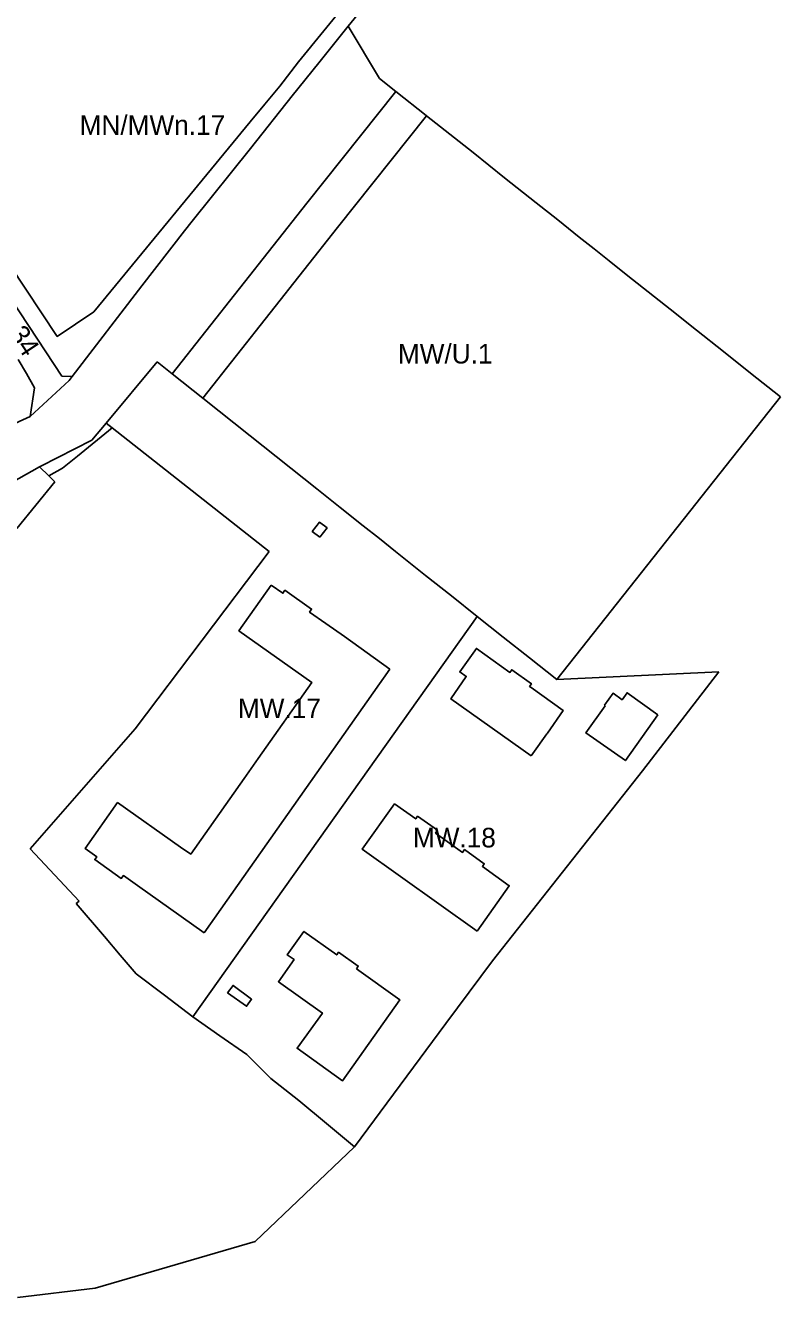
# Model space of a CAD drawing. Extents: x 7425067 to 7426806, y 5549054 to 5550619.
# Drawn here: x 7426541.6 to 7426734.3, y 5549087.4 to 5549411.9 of the extents above; entities that cross this region are included whole.
import ezdxf

# ---------------------------------------------------------------- set-up
doc = ezdxf.new("R2010")
doc.units = 0
for name, color, linetype in [('LIN_Linia Zabudowy Nieprzekraczalna', 7, 'Continuous'), ('LIN_linia zabudowy obowiązująca', 7, 'Continuous'), ('LIN_linie_rozgraniczajace', 7, 'Continuous'), ('TXT_Oznaczenia_przeznaczen', 7, 'Continuous')]:
    doc.layers.add(name, color=color, linetype=linetype)

msp = doc.modelspace()

# ---------------------------------------------------------------- linework, layer by layer
at = {"layer": 'LIN_Linia Zabudowy Nieprzekraczalna'}
for points in [[(7426559.05, 5549338.85), (7426598.94, 5549387.25), (7426602.65, 5549391.8), (7426606.54, 5549396.35), (7426611.3, 5549402.56), (7426623.41, 5549417.42)], [(7426509.4701, 5549393.1024), (7426549.7, 5549332.54), (7426559.05, 5549338.85)], [(7426643.961, 5549388.8438), (7426621.2029, 5549360.3434), (7426586.8566, 5549316.8017)], [(7426563.6817, 5549309.2654), (7426554.9095, 5549301.9812), (7426551.0535, 5549298.9547), (7426547.549, 5549296.9622)]]:
    msp.add_lwpolyline(points, dxfattribs=at)
at = {"layer": 'LIN_linia zabudowy obowiązująca'}
for points in [[(7426616.69, 5549281.34), (7426618.56, 5549283.7), (7426616.65, 5549285.2), (7426614.79, 5549282.84), (7426616.69, 5549281.34)], [(7426604.32, 5549269.15), (7426596.08, 5549257.47), (7426614.72, 5549244.29), (7426601.03, 5549224.89), (7426597.41, 5549219.8), (7426583.77, 5549200.51), (7426581.19, 5549202.33), (7426565.1, 5549213.65), (7426556.83, 5549201.99), (7426559.79, 5549199.83), (7426559.27, 5549199.13), (7426566.03, 5549194.32), (7426566.59, 5549195.06), (7426570.77, 5549192.09), (7426575.49, 5549188.76), (7426587.21, 5549180.44)], [(7426634.62, 5549247.73), (7426622.99, 5549256), (7426618.29, 5549259.3), (7426614.11, 5549262.27), (7426614.61, 5549263.01), (7426607.82, 5549267.8), (7426607.29, 5549267.07), (7426604.32, 5549269.15)], [(7426670.64, 5549225.56), (7426671.06, 5549226.15), (7426674.69, 5549231.23), (7426674.8, 5549231.41), (7426678.85, 5549237.13), (7426670.6318, 5549243.0425), (7426670.26, 5549243.31), (7426670.74, 5549243.98), (7426665.73, 5549247.54), (7426665.25, 5549246.87), (7426656.68, 5549252.97), (7426652.45, 5549247.01), (7426654.12, 5549245.83), (7426650.2, 5549240.12), (7426670.64, 5549225.56)], [(7426587.21, 5549180.44), (7426634.62, 5549247.73)], [(7426703.04, 5549236.06), (7426695.15, 5549241.68), (7426693.89, 5549239.91), (7426691.58, 5549241.54), (7426689.41, 5549238.49), (7426689.59, 5549238.37)], [(7426689.59, 5549238.37), (7426684.66, 5549231.42), (7426694.74, 5549224.37), (7426703.04, 5549236.06)], [(7426656.9, 5549180.9), (7426665.09, 5549192.46), (7426658.22, 5549197.38), (7426658.69, 5549198.05), (7426653.67, 5549201.68), (7426653.17, 5549200.97), (7426646.27, 5549205.88), (7426646.75, 5549206.59), (7426641.68, 5549210.18), (7426641.2, 5549209.5), (7426635.8, 5549213.33), (7426627.57, 5549201.75), (7426656.9, 5549180.9)], [(7426626.06, 5549171.24), (7426626.55, 5549171.97), (7426621.52, 5549175.5), (7426621.04, 5549174.83), (7426612.66, 5549180.79), (7426608.43, 5549174.83), (7426610.14, 5549173.62), (7426606.15, 5549167.99), (7426617.39, 5549160), (7426610.92, 5549151), (7426622.53, 5549142.72), (7426637.17, 5549163.35), (7426626.06, 5549171.24)], [(7426593.17, 5549165.17), (7426598.02, 5549161.74), (7426599.29, 5549163.49), (7426594.57, 5549167.02), (7426593.17, 5549165.17)]]:
    msp.add_lwpolyline(points, dxfattribs=at)
at = {"layer": 'LIN_linie_rozgraniczajace'}
for points in [[(7426626.2246, 5549414.4685), (7426623.958, 5549411.6537)], [(7426616.49, 5549402.36), (7426623.958, 5549411.6537)], [(7426623.958, 5549411.6537), (7426631.93, 5549398.36)], [(7426609.7, 5549393.89), (7426616.49, 5549402.36)], [(7426631.93, 5549398.36), (7426636.1178, 5549395.0476), (7426643.89, 5549388.9)], [(7426599.01, 5549380.5), (7426609.7, 5549393.89)], [(7426613.37, 5549366.56), (7426636.1178, 5549395.0476)], [(7426643.89, 5549388.9), (7426643.961, 5549388.8438), (7426655.85, 5549379.44)], [(7426584.13, 5549361.94), (7426599.01, 5549380.5)], [(7426655.85, 5549379.44), (7426663.89, 5549373.03)], [(7426663.89, 5549373.03), (7426671.93, 5549366.62)], [(7426579.0286, 5549323.0245), (7426613.37, 5549366.56)], [(7426671.93, 5549366.62), (7426677.44, 5549362.26)], [(7426582.16, 5549359.48), (7426584.13, 5549361.94)], [(7426677.44, 5549362.26), (7426682.94, 5549357.89)], [(7426571.27, 5549345.42), (7426582.16, 5549359.48)], [(7426682.94, 5549357.89), (7426686.75, 5549354.86)], [(7426686.75, 5549354.86), (7426690.57, 5549351.84)], [(7426690.57, 5549351.84), (7426694.95, 5549348.36)], [(7426552.72, 5549321.35), (7426553.4812, 5549322.3377), (7426571.27, 5549345.42)], [(7426694.95, 5549348.36), (7426699.34, 5549344.89)], [(7426537.79, 5549342.29), (7426544.645, 5549331.83)], [(7426699.34, 5549344.89), (7426706.11, 5549339.51)], [(7426706.11, 5549339.51), (7426712.88, 5549334.14)], [(7426712.88, 5549334.14), (7426719.76, 5549328.68)], [(7426544.645, 5549331.83), (7426550.8374, 5549322.381)], [(7426539.73, 5549326.66), (7426541.835, 5549323.065)], [(7426562.19, 5549310.44), (7426575.21, 5549326.06)], [(7426575.21, 5549326.06), (7426579.0286, 5549323.0245)], [(7426719.76, 5549328.68), (7426726.64, 5549323.22)], [(7426541.835, 5549323.065), (7426543.94, 5549319.47)], [(7426598.91, 5549307.22), (7426586.8566, 5549316.8017), (7426579.0286, 5549323.0245)], [(7426726.64, 5549323.22), (7426734.33, 5549317.11)], [(7426542.78, 5549312.14), (7426552.72, 5549321.35)], [(7426543.94, 5549319.47), (7426542.78, 5549312.14)], [(7426550.8374, 5549322.381), (7426553.4812, 5549322.3377)], [(7426734.33, 5549317.11), (7426677.18, 5549245.04)], [(7426542.78, 5549312.14), (7426532.06, 5549307.31)], [(7426558.54, 5549306.06), (7426562.19, 5549310.44)], [(7426562.19, 5549310.44), (7426563.6817, 5549309.2654), (7426582.98, 5549294.07)], [(7426598.91, 5549307.22), (7426615.95, 5549293.67)], [(7426545.49, 5549299.47), (7426558.54, 5549306.06)], [(7426536.6, 5549294.43), (7426545.2146, 5549299.3138), (7426545.49, 5549299.47)], [(7426545.2146, 5549299.3138), (7426547.549, 5549296.9622), (7426549.07, 5549295.43)], [(7426539.355, 5549283.58), (7426549.07, 5549295.43)], [(7426582.98, 5549294.07), (7426603.77, 5549277.7)], [(7426615.95, 5549293.67), (7426621.885, 5549288.96)], [(7426621.885, 5549288.96), (7426627.82, 5549284.25)], [(7426627.82, 5549284.25), (7426631.94, 5549280.975)], [(7426631.94, 5549280.975), (7426636.06, 5549277.7)], [(7426603.77, 5549277.7), (7426569.59, 5549232.5)], [(7426636.06, 5549277.7), (7426639.9, 5549274.655)], [(7426639.9, 5549274.655), (7426643.74, 5549271.61)], [(7426643.74, 5549271.61), (7426650.325, 5549266.375)], [(7426650.325, 5549266.375), (7426656.91, 5549261.14)], [(7426584.31, 5549159.01), (7426656.91, 5549261.14)], [(7426656.91, 5549261.14), (7426663.565, 5549255.85)], [(7426663.565, 5549255.85), (7426670.22, 5549250.56)], [(7426670.22, 5549250.56), (7426677.18, 5549245.04)], [(7426677.18, 5549245.04), (7426718.58, 5549247.04)], [(7426718.58, 5549247.04), (7426699.07, 5549221.74)], [(7426569.59, 5549232.5), (7426542.82, 5549201.87)], [(7426699.07, 5549221.74), (7426660.81, 5549173.3)], [(7426542.82, 5549201.87), (7426555.26, 5549188.53)], [(7426555.26, 5549188.53), (7426554.57, 5549187.94)], [(7426554.57, 5549187.94), (7426561.74, 5549179.54)], [(7426561.74, 5549179.54), (7426565.795, 5549174.785)], [(7426565.795, 5549174.785), (7426569.85, 5549170.03)], [(7426660.81, 5549173.3), (7426648.85, 5549157.31)], [(7426569.85, 5549170.03), (7426577.08, 5549164.52)], [(7426577.08, 5549164.52), (7426584.31, 5549159.01)], [(7426584.31, 5549159.01), (7426591.21, 5549154.215)], [(7426648.85, 5549157.31), (7426625.56, 5549125.89)], [(7426591.21, 5549154.215), (7426598.11, 5549149.42)], [(7426598.11, 5549149.42), (7426604.18, 5549143.33)], [(7426604.18, 5549143.33), (7426607.77, 5549140.52)], [(7426607.77, 5549140.52), (7426611.36, 5549137.71)], [(7426611.36, 5549137.71), (7426618.46, 5549131.8)], [(7426618.46, 5549131.8), (7426625.56, 5549125.89)], [(7426625.56, 5549125.89), (7426600.21, 5549101.71)], [(7426600.21, 5549101.71), (7426559.4, 5549089.83)], [(7426559.4, 5549089.83), (7426539.6, 5549087.43)]]:
    msp.add_lwpolyline(points, dxfattribs=at)

# ---------------------------------------------------------------- texts
at = {"layer": 'TXT_Oznaczenia_przeznaczen'}
for s, p in [('MN/MWn.17', (7426555.4195, 5549383.958)), ('MW/U.1', (7426636.6555, 5549325.645)), ('MW.17', (7426595.8151, 5549235.2009)), ('MW.18', (7426640.4784, 5549202.2276))]:
    msp.add_text(s, height=5, dxfattribs=at).set_placement(p)
msp.add_text('KDD.34', height=5, rotation=303.67634, dxfattribs=at).set_placement((7426528.3359, 5549346.4871))

doc.saveas('drawing.dxf')
